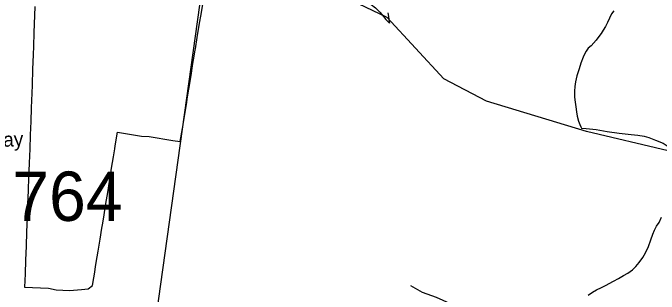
# Model space of a CAD drawing. Extents: x 2001466 to 2224147, y 644118 to 847247.
# Drawn here: x 2051357 to 2055654, y 695772 to 697641 of the extents above; entities that cross this region are included whole.
import ezdxf

# ---------------------------------------------------------------- set-up
doc = ezdxf.new("R2010")
doc.units = 0
for name, color, linetype in [('Exist Boundary Political City Limit New Hole', 7, 'Continuous'), ('Exist Hydrographic Creek Single Shore', 7, 'Continuous'), ('Exist Hydrographic Misc Water Feature', 7, 'Continuous'), ('Exist Road Non-System Type 51', 7, 'Continuous'), ('Exist Road Non-System Type 51 Label', 7, 'Continuous'), ('Exist Road Secondary Structure Standard Bridge Number Label', 7, 'Continuous'), ('Exist Utilities Electrical Transmission Line', 7, 'Continuous'), ('Map Preparation Boundary City Limit Buffer Line', 7, 'Continuous')]:
    doc.layers.add(name, color=color, linetype=linetype)

msp = doc.modelspace()

# ---------------------------------------------------------------- linework, layer by layer
at = {"layer": 'Exist Boundary Political City Limit New Hole'}
for points in [[(2051898.2, 695904.8), (2051908.6, 695968.1), (2051917, 696019.1), (2051923.1, 696056.9), (2051936, 696135.9), (2051948.1, 696209.9), (2051953.5, 696242.8), (2051962.5, 696298.7), (2051974.6, 696372.8), (2051986.8, 696446.8), (2051994.1, 696492.1), (2052001.1, 696535.6), (2052002.5, 696543.8), (2052013.2, 696609.6), (2052025.4, 696683.6), (2052034.2, 696738), (2052037.4, 696757.6), (2052053.1, 696847.2), (2052211, 696821.8), (2052262.2, 696818.6), (2052420.2, 696793.2), (2052469.6, 696785.2), (2052483.9, 696872.8), (2052510, 697032), (2052518.1, 697082.3), (2052535, 697185.9), (2052543.9, 697240.4), (2052552, 697289.6), (2052558.4, 697329.2), (2052568.9, 697393.2), (2052570.2, 697401.6), (2052582.6, 697477.8), (2052598.2, 697573.4), (2052607.5, 697630), (2052632.6, 697783.1)], [(2051503.1, 697682.6), (2051496.1, 697508.7), (2051492.6, 697420.3), (2051490.6, 697362.3), (2051487.4, 697267.6), (2051483.9, 697160.9), (2051482, 697107.6), (2051478.8, 697010.7), (2051475.5, 696919.1), (2051472.2, 696829.9), (2051468.8, 696731.9), (2051467.4, 696693.6), (2051464.1, 696639.4), (2051460.9, 696549.4), (2051457.5, 696459.5), (2051454.2, 696369.6), (2051451, 696279.6), (2051447.6, 696184.6), (2051444, 696089.8), (2051440.5, 695996.9), (2051437.1, 695907), (2051433.8, 695817.1), (2051592.9, 695811.2), (2051643.4, 695799.1), (2051732.4, 695795.8), (2051812.2, 695802.6), (2051856.4, 695806.2), (2051885.9, 695828.7), (2051894.1, 695879.2), (2051898.2, 695904.8)]]:
    msp.add_lwpolyline(points, dxfattribs=at)
at = {"layer": 'Exist Hydrographic Creek Single Shore'}
msp.add_lwpolyline([(2055715, 696724.5), (2055172.2, 696852.8), (2054505.2, 697053.5), (2054222.2, 697203.6), (2053846.2, 697611.5), (2053654.2, 697700.7), (2053245.2, 698024), (2053162.3, 698117.6)], dxfattribs=at)
at = {"layer": 'Exist Hydrographic Misc Water Feature'}
for points in [[(2053158.6, 698106.7), (2053160.5, 698102.8), (2053184.5, 698063.1), (2053218.9, 698027), (2053258.7, 697993), (2053294.6, 697963.2), (2053342.6, 697925.1), (2053390.5, 697889.4), (2053438.7, 697857.3), (2053506.8, 697819.5), (2053536.7, 697805.6), (2053575.1, 697789.7), (2053621, 697769.7), (2053668.8, 697745.8), (2053700.8, 697726), (2053739.1, 697697.9), (2053767, 697674.1), (2053797.2, 697646), (2053813.4, 697628.2), (2053837.1, 697598.2), (2053860.9, 697572.3)], [(2053849.2, 697642.2), (2053855, 697618.2), (2053857.2, 697596.4), (2053859.3, 697580.3), (2053860.9, 697572.3)], [(2055353.1, 697655.1), (2055338.5, 697635), (2055325, 697607), (2055311.1, 697577.1), (2055296.9, 697550.8), (2055283.2, 697527), (2055268.8, 697504.8), (2055253.2, 697484.9), (2055235.2, 697460.8), (2055201.4, 697423), (2055183.3, 697406.6), (2055169.4, 697386.9), (2055159.3, 697370.5), (2055149.5, 697346.9), (2055133.5, 697306.7), (2055121.6, 697268.8), (2055107.4, 697222.7), (2055097.8, 697182.7), (2055093.7, 697152.5), (2055091.9, 697120.8), (2055091.9, 697080.6), (2055096, 697046.7), (2055099.9, 697016.5), (2055104.2, 696982.6), (2055108.3, 696954.8), (2055117.9, 696920.9), (2055126.3, 696898.9), (2055134.1, 696882.7), (2055138.4, 696874.8)], [(2055138.4, 696874.8), (2055168.1, 696872.7), (2055234.6, 696865.1), (2055308.6, 696853.1), (2055388.2, 696841.4), (2055468.5, 696833.3), (2055512.2, 696827.5), (2055554, 696821.5), (2055586, 696811.8), (2055630.1, 696795.8), (2055680.6, 696774), (2055714.6, 696753.8), (2055754.2, 696731.9), (2055782.5, 696717.9), (2055800.3, 696707.9), (2055824.5, 696702.2), (2055850.5, 696698.2), (2055864.7, 696698.2)], [(2055182.5, 695765.2), (2055212.2, 695785.1), (2055238.3, 695799.4), (2055270.2, 695815.2), (2055298.1, 695829.2), (2055350, 695857.5), (2055384.1, 695875.4), (2055418.1, 695895.5), (2055446.2, 695911.5), (2055476.3, 695933.6), (2055499.9, 695955.6), (2055521.6, 695981.5), (2055546, 696015.6), (2055563.7, 696045.7), (2055583.6, 696087.7), (2055599.4, 696132), (2055611.7, 696169.9), (2055623.1, 696195.7), (2055637.3, 696222), (2055653.5, 696247.9), (2055671.1, 696282.1)]]:
    msp.add_lwpolyline(points, dxfattribs=at)
at = {"layer": 'Exist Road Non-System Type 51'}
msp.add_lwpolyline([(2054000.1, 695828.1), (2054077.8, 695783.7), (2054172.2, 695750.4), (2054261, 695711.5), (2054355.4, 695650.4), (2054533, 695511.5)], dxfattribs=at)
at = {"layer": 'Exist Utilities Electrical Transmission Line'}
msp.add_lwpolyline([(2052670.2, 698200.4), (2052666.6, 698141.7), (2052640.9, 697981.6), (2052597.4, 697691.7), (2052308.7, 695631.5), (2052206, 694903.6), (2052052.9, 693815.5)], dxfattribs=at)
at = {"layer": 'Map Preparation Boundary City Limit Buffer Line'}
for points in [[(2051898.2, 695904.8), (2051908.6, 695968.1), (2051917, 696019.1), (2051923.1, 696056.9), (2051936, 696135.9), (2051948.1, 696209.9), (2051953.5, 696242.8), (2051962.5, 696298.7), (2051974.6, 696372.8), (2051986.8, 696446.8), (2051994.1, 696492.1), (2052001.1, 696535.6), (2052002.5, 696543.8), (2052013.2, 696609.6), (2052025.4, 696683.6), (2052034.2, 696738), (2052037.4, 696757.6), (2052053.1, 696847.2), (2052211, 696821.8), (2052262.2, 696818.6), (2052420.2, 696793.2), (2052469.6, 696785.2), (2052483.9, 696872.8), (2052510, 697032), (2052518.1, 697082.3), (2052535, 697185.9), (2052543.9, 697240.4), (2052552, 697289.6), (2052558.4, 697329.2), (2052568.9, 697393.2), (2052570.2, 697401.6), (2052582.6, 697477.8), (2052598.2, 697573.4), (2052607.5, 697630), (2052632.6, 697783.1)], [(2051503.1, 697682.6), (2051496.1, 697508.7), (2051492.6, 697420.3), (2051490.6, 697362.3), (2051487.4, 697267.6), (2051483.9, 697160.9), (2051482, 697107.6), (2051478.8, 697010.7), (2051475.5, 696919.1), (2051472.2, 696829.9), (2051468.8, 696731.9), (2051467.4, 696693.6), (2051464.1, 696639.4), (2051460.9, 696549.4), (2051457.5, 696459.5), (2051454.2, 696369.6), (2051451, 696279.6), (2051447.6, 696184.6), (2051444, 696089.8), (2051440.5, 695996.9), (2051437.1, 695907), (2051433.8, 695817.1), (2051592.9, 695811.2), (2051643.4, 695799.1), (2051732.4, 695795.8), (2051812.2, 695802.6), (2051856.4, 695806.2), (2051885.9, 695828.7), (2051894.1, 695879.2), (2051898.2, 695904.8)]]:
    msp.add_lwpolyline(points, dxfattribs=at)

# ---------------------------------------------------------------- texts
at = {"layer": 'Exist Road Non-System Type 51 Label'}
msp.add_text('Sandy Pointe Way', height=95, rotation=2.2108, dxfattribs=at).set_placement((2050382.9, 696715.4))
at = {"layer": 'Exist Road Secondary Structure Standard Bridge Number Label'}
msp.add_text('764', height=328.08, dxfattribs=at).set_placement((2051353.2, 696258.1))

doc.saveas('drawing.dxf')
